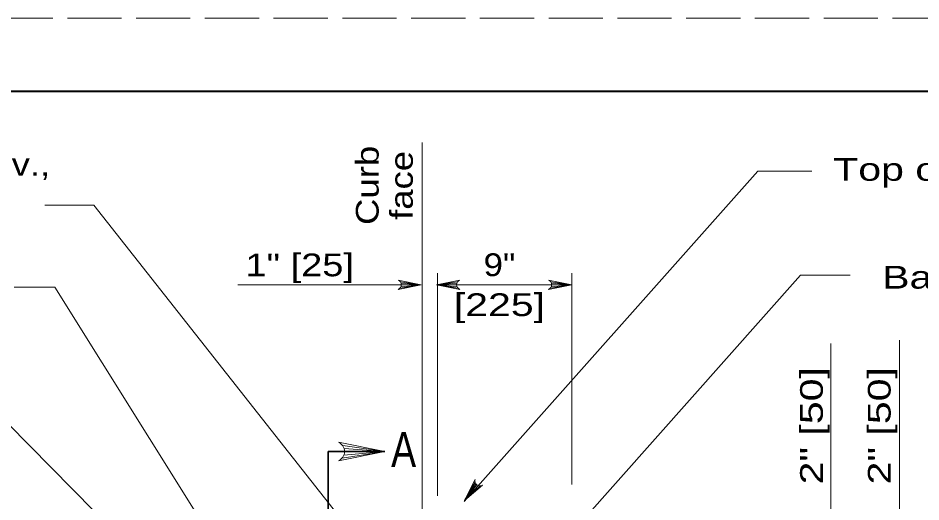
# Model space of a CAD drawing. Extents: x 1352.5 to 1386.5, y 735.9 to 779.9.
# Drawn here: x 1375.42 to 1381.62, y 776.6 to 779.92 of the extents above; entities that cross this region are included whole.
import ezdxf
from ezdxf.enums import TextEntityAlignment as Align

# ---------------------------------------------------------------- set-up
doc = ezdxf.new("R2010")
doc.units = 0
doc.header["$LTSCALE"] = 0.062
doc.linetypes.add('LONG_DASHED', pattern=[7.5, 6, -1.5])
doc.layers.add('1', color=7, linetype='Continuous', lineweight=13)

msp = doc.modelspace()

# ---------------------------------------------------------------- linework, layer by layer
at = {"layer": '1', "lineweight": 25}
msp.add_line((1354.513, 779.41967), (1386.013, 779.41967), dxfattribs=at)
at = {"layer": '1'}
for p, q in [((1378.19275, 776.37192), (1378.19275, 779.06733)), ((1378.48042, 776.60567), (1380.49567, 778.87042)), ((1380.86733, 778.87042), (1380.49567, 778.87042)), ((1378.0425, 778.11133), (1378.18675, 778.09117)), ((1378.4355, 778.11133), (1378.29133, 778.09117)), ((1378.29792, 776.64467), (1378.29792, 778.17075)), ((1378.83567, 775.96142), (1380.79, 778.15767)), ((1379.07458, 778.11133), (1379.21883, 778.09117)), ((1379.21883, 776.72283), (1379.21883, 778.17075)), ((1380.79, 778.15767), (1381.13092, 778.15767)), ((1378.18675, 778.09117), (1376.92808, 778.09117)), ((1378.04083, 778.06883), (1378.18675, 778.09117)), ((1378.04633, 778.07817), (1378.18675, 778.09117)), ((1378.04742, 778.10133), (1378.18675, 778.09117)), ((1378.04892, 778.09117), (1378.18675, 778.09117)), ((1378.43067, 778.10133), (1378.29133, 778.09117)), ((1378.42917, 778.09117), (1378.29133, 778.09117)), ((1378.43175, 778.07817), (1378.29133, 778.09117)), ((1378.43725, 778.06883), (1378.29133, 778.09117)), ((1379.21883, 778.09117), (1378.29133, 778.09117)), ((1379.07292, 778.06883), (1379.21883, 778.09117)), ((1379.07842, 778.07817), (1379.21883, 778.09117)), ((1379.0795, 778.10133), (1379.21883, 778.09117)), ((1379.081, 778.09117), (1379.21883, 778.09117)), ((1380.99775, 776.01483), (1380.99775, 777.68825)), ((1381.46975, 776.35067), (1381.46975, 777.71117)), ((1377.64392, 776.90325), (1377.93575, 776.94783)), ((1377.64733, 776.98825), (1377.93575, 776.94783)), ((1377.655, 776.92192), (1377.93575, 776.94783)), ((1377.65708, 776.96825), (1377.93575, 776.94783)), ((1377.66008, 776.94783), (1377.93575, 776.94783)), ((1378.55567, 776.73725), (1378.48317, 776.611)), ((1378.56058, 776.72725), (1378.48317, 776.611)), ((1378.56775, 776.71983), (1378.48317, 776.611)), ((1378.5795, 776.71392), (1378.48317, 776.611)), ((1378.59025, 776.7125), (1378.48317, 776.611))]:
    msp.add_line(p, q, dxfattribs=at)
at = {"layer": '1', "lineweight": 35}
for p, q in [((1377.54633, 776.94783), (1377.93575, 776.94783)), ((1377.54633, 773.4095), (1377.54633, 776.94783))]:
    msp.add_line(p, q, dxfattribs=at)
at = {"layer": '1', "linetype": 'LONG_DASHED'}
msp.add_lwpolyline([(1352.513, 757.91967), (1386.513, 757.91967), (1386.513, 779.91967), (1352.513, 779.91967)], close=True, dxfattribs=at)
at = {"layer": '1', "lineweight": 40}
msp.add_lwpolyline([(1354.513, 779.41967), (1386.013, 779.41967), (1386.013, 758.41967), (1354.513, 758.41967)], close=True, dxfattribs=at)
msp.add_lwpolyline([(1354.513, 779.41967), (1386.013, 779.41967), (1386.013, 758.41967), (1354.513, 758.41967)], close=True, dxfattribs=at)
at = {"layer": '1'}
for points in [[(1378.221, 775.745), (1375.93775, 778.63742), (1375.60342, 778.63742)], [(1378.02742, 778.05925), (1378.18675, 778.09117), (1378.02742, 778.123)], [(1378.45058, 778.05925), (1378.29133, 778.09117), (1378.45058, 778.123)], [(1379.0595, 778.05925), (1379.21883, 778.09117), (1379.0595, 778.123)], [(1376.97058, 776.00042), (1375.67183, 778.07408), (1375.39275, 778.07408)], [(1376.53433, 775.93808), (1375.19883, 777.28867), (1375.01275, 777.28867)], [(1377.61717, 776.88417), (1377.93575, 776.94783), (1377.61717, 777.01158)], [(1378.60608, 776.71725), (1378.48317, 776.611), (1378.55575, 776.75633)]]:
    msp.add_lwpolyline(points, dxfattribs=at)
for centre, radius, start, end in [((1378.01458, 778.09116), 0.03438, 292.08605, 67.91218), ((1378.46349, 778.09116), 0.03438, 112.08782, 247.91395), ((1379.04668, 778.09116), 0.03438, 292.08605, 67.91218), ((1377.59144, 776.94793), 0.06876, 292.08605, 67.91218), ((1378.58875, 776.74697), 0.03438, 164.238, 300.06413)]:
    msp.add_arc(centre, radius, start, end, dxfattribs=at)

# ---------------------------------------------------------------- texts
for s, height, width, p in [('Location of grate, elev.,', 0.156, 1.2, (1373.03675, 778.83858)), ('Top of curb & casting', 0.156, 1.35, (1381.01417, 778.80442)), ('1" [25]', 0.156, 1.25, (1376.97942, 778.14942)), ('Back of curb', 0.156, 1.35, (1381.35008, 778.06483)), ('A', 0.24, 0.8, (1377.97958, 776.84258))]:
    msp.add_text(s, height=height, dxfattribs=dict(at, width=width)).set_placement(p)
at = {"layer": '1', "width": 1.2}
for s, p in [('Curb', (1377.89367, 778.77258)), ('face', (1378.12833, 778.77258))]:
    msp.add_text(s, height=0.156, rotation=90, dxfattribs=at).set_placement(p, align=Align.CENTER)
at = {"layer": '1'}
for s, width, p in [('9"', 1.15, (1378.723, 778.1505)), ('[225]', 1.35, (1378.723, 777.8765))]:
    msp.add_text(s, height=0.156, dxfattribs=dict(at, width=width)).set_placement(p, align=Align.CENTER)
at = {"layer": '1', "width": 1.35}
for p in [(1380.94292, 776.72225), (1381.40817, 776.72225)]:
    msp.add_text('2" [50]', height=0.156, rotation=90, dxfattribs=at).set_placement(p)

doc.saveas('drawing.dxf')
